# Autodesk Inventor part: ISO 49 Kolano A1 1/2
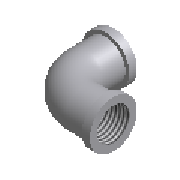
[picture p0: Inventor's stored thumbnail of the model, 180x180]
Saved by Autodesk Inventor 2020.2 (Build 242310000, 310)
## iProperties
Manager: www.cadconsulting.pl
Company: Fabian Stasiak CAD Consulting
Created: 2014-02
Part Number: ISO 49 Kolano A1 1/2
Material: Żelazo, ciągliwe
Description: Elementy z żeliwa ciągliwego - Kolanka A1
Document SubType Name: Modeling
Standard: ISO 49
Designer: F.Stasiak
Standard Revision: Second edition 1994-12-15
Standards Organization: ISO
Language: pl-PL
Size Designation: 1/2
Categories: <MemberInstance><Categories><Category DisplayName="Rury cienko- i grubościenne" InternalName="4347fa0f-2144-441d-94cd-e3e15c92b736" Mnemonic="TUBEANDPIPE"><Cate
Density: 7.15 g/cm^3
Appearance: Częściowo polerowana
Catalog Web Link: www.expertbooks.pl
NAME: PIPING: ISO 49 Elbow A1
DATA: <meta><inlinegroups number="0" deflen="0"></inlinegroups><connections number="2"></connections><angles><a>1.57079632679489</a></angles></meta>
IsCustomPart: 0
Author: F.Stasiak
Subject: Zbiór ćwiczeń. Autodesk Inventor 2020. Kurs Professional
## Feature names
1. Revolution1
2. Revolution2
3. Sweep1
## Parameters: a = 28 mm, MD = 18.631 mm, H = 26.04 mm, d0 = 18.631 mm, d1 = 26.04 mm, d2 = 4.34 mm, d3 = 13 mm, d4 = 0.3124 mm, d26 = 90 deg, d5 = 18.631 mm, d6 = 21.7 mm, d7 = 26.04 mm, d8 = 4.34 mm, d9 = 13 mm, d10 = 0.3124 mm, d37 = 90 deg, EE = 4.34 mm, D = 21.7 mm, z = 15 mm, d11 = 21.7 mm, d12 = 28 mm, d13 = 21.7 mm, d14 = 0, d83 = 25.4 mm, d84 = 0, d85 = 25.4 mm, d86 = 0, d15 = 28 mm, d88 = 0, Size_Designation = 5 mm
